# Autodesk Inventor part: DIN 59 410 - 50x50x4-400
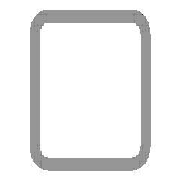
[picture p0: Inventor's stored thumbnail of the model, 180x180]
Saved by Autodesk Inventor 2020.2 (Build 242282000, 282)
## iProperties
Manager: www.cadconsulting.pl
Company: Fabian Stasiak CAD Consulting
Created: 2015-01
Part Number: DIN 59 410 - 50x50x4-400
Material: Stal, miękka
Description: Rurki stalowe o przekroju kwadratowym formowane na gorąco
Document SubType Name: Modellieren
Standard: DIN
Designer: F.Stasiak
Standards Organization: DIN
Language: pl-PL
Size Designation: 50x50x4
Categories: <MemberInstance><Categories><Category DisplayName="Kształtowniki konstrukcyjne" InternalName="089c4875-fa83-4c05-b084-43b9cc11f5ed" Mnemonic="GRDR"><CategoryPar
Stock Number: 50x50x4
Density: 7.85 g/cm^3
Appearance: Częściowo polerowana
Mass: 2181.66 g
Surface Area: 1403.49 cm^2
Volume: 277.919 cm^3
Catalog Web Link: www.expertbooks.pl
_CCFamilyMember: 40
_CCFamilyDisplayName: DIN 59410 (Kwadrat) - Rurki stalowe o przekroju kwadratowym formowane na gorąco
_FrameMemberDoc: Frame Member File
_Version: 15.0.0
_GetPNFromCC: 1
G_W: 50,000 mm
G_H: 50,000 mm
+B4833808-6D84-4239-9518-E98576444887+CUTDETAIL1: Wytnij
+20D6724A-F615-45A8-9C08-C04307772C54+CUTDETAIL2: Wytnij
G_L: 400,000 mm
IsCustomPart: 1
Author: F.Stasiak
Subject: Zbiór ćwiczeń. Autodesk Inventor 2020. Kurs Professional
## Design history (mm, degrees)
node "Płaszczyzna początkowa"
node "Płaszczyzna końcowa"
sketch "Szkic"
  geometry: L1 (-17, 25)-(17, 25); L2 (25, 17)-(25, -17); L3 (17, -25)-(-17, -25); L4 (-25, -17)-(-25, 17); L5 (-37.32, 0)-(37.32, 0) reference; L6 (0, -37.32)-(0, 37.32) reference; L7 (-17, 21)-(17, 21); L8 (21, 17)-(21, -17); L9 (17, -21)-(-17, -21); L10 (-21, -17)-(-21, 17); A1 r 8 centre (-17, 17) between (-17, 25) and (-25, 17); A2 r 8 centre (17, 17) between (25, 17) and (17, 25); A3 r 8 centre (17, -17) between (17, -25) and (25, -17); A4 r 8 centre (-17, -17) between (-25, -17) and (-17, -25); A5 r 4 centre (-17, 17) between (-17, 21) and (-21, 17); A6 r 4 centre (17, 17) between (21, 17) and (17, 21); A7 r 4 centre (17, -17) between (17, -21) and (21, -17); A8 r 4 centre (-17, -17) between (-21, -17) and (-17, -21); 3 further points
  constraints: 16 end point, 16 point on circle, 8 centre point, 8 tangent, 6 point on line, 4 parallel, 3 equal radius, 3 perpendicular, 1 horizontal, 7 other
  dimensions: "b" = 50 distance of point (-25, 25) point (25, 25); "msp_r" = 8 radius of A1 (= 2 x ParT); "d8" = 25 distance between parallel lines of L4 L6 (= d9); "d9" = 25 distance between parallel lines of L3 L5 (= 0.5 x b); "d10" = 4 distance between parallel lines of L3 L9 (= ParT)
extrude "Bryła" new body sketch "Szkic" taper "d4" = 0 deg; stored distance "NLG" = 10
node "Driven Length"
  sketch "Sketch2"
    geometry: L1 (0, 0)-(10, 0) reference
    constraints: 2 end point, 1 horizontal
  workplane "Work Plane3"
  sketch "Sketch3"
    geometry: L1 (-2, 25)-(12, 25) reference; L2 (-2, 425)-(12, 425) reference
    dimensions: "d14" = 400 distance between parallel lines of L1 L2 (derived)
node "Płaszczyzna konstrukcyjna4"
feature "Podział1"
node "Płaszczyzna konstrukcyjna5"
feature "Podział2"
body "Solid1"
other parameters: "ParT" = 4, "G_OFFSET_START" = -25 [user parameter; used in 1 equation term], "G_OFFSET_END" = -25 [user parameter; used in 1 equation term], "d11" = 25 (= -G_OFFSET_START), "d12" = 425 (= G_OFFSET_END + B_L), "G_L" = 400 (= d14) [user parameter], "d13" = 90 deg
